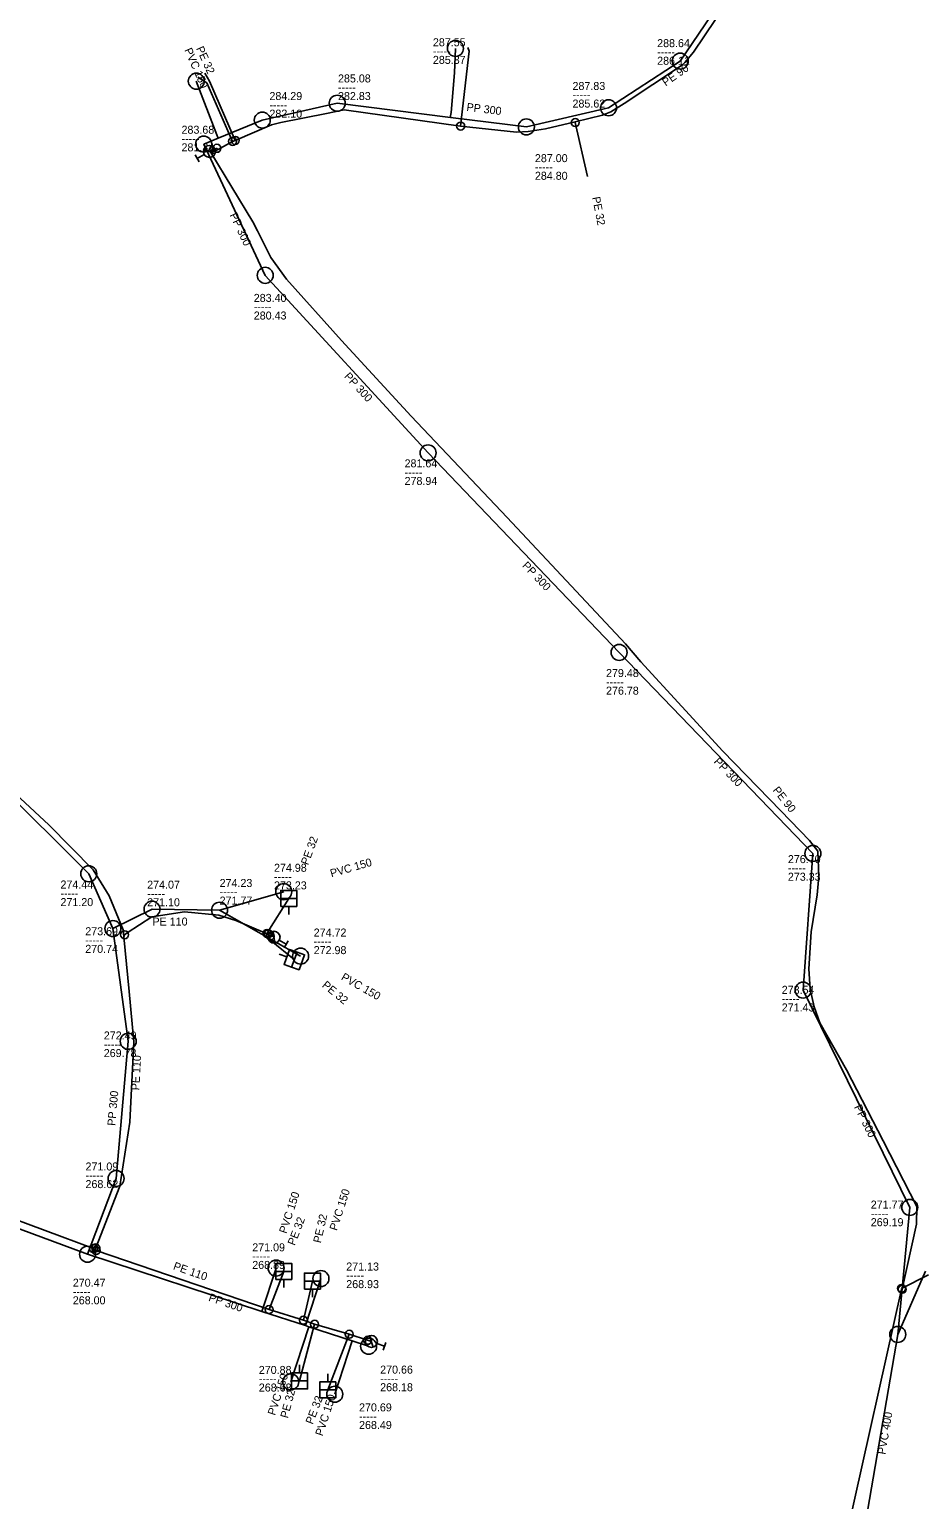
# Model space of a CAD drawing. Extents: x -770828 to -770111, y -1050344 to -1049447.
# Drawn here: x -770619.1 to -770507.8, y -1049725.3 to -1049541.6 of the extents above; entities that cross this region are included whole.
import ezdxf

# ---------------------------------------------------------------- set-up
doc = ezdxf.new("R2010")
doc.units = 0
doc.layers.add('Level 0', color=7, linetype='Continuous')

msp = doc.modelspace()

# ---------------------------------------------------------------- linework, layer by layer
at = {"layer": 'Level 0'}
for p, q in [((-770532.05, -1049537.18), (-770537.74, -1049545.57)), ((-770536.06, -1049544.45), (-770531.94, -1049538.32)), ((-770565.83, -1049543.99), (-770565.94, -1049547.05)), ((-770564.1, -1049544.35), (-770565.18, -1049553.69)), ((-770564.29, -1049543.88), (-770564.1, -1049544.35)), ((-770537.16, -1049545.75), (-770536.06, -1049544.45)), ((-770537.74, -1049545.57), (-770546.69, -1049551.41)), ((-770544.73, -1049550.86), (-770537.57, -1049546.11)), ((-770537.57, -1049546.11), (-770537.16, -1049545.75)), ((-770598.22, -1049548.08), (-770595.67, -1049554.78)), ((-770598.04, -1049547.59), (-770596.92, -1049548.29)), ((-770597.14, -1049547.08), (-770596.59, -1049548.1)), ((-770596.92, -1049548.29), (-770593.68, -1049555.6)), ((-770596.59, -1049548.1), (-770593.36, -1049555.48)), ((-770565.94, -1049547.05), (-770566.37, -1049551.98)), ((-770580.61, -1049550.84), (-770589.97, -1049552.94)), ((-770587.67, -1049553.23), (-770581.96, -1049552.1)), ((-770581.96, -1049552.1), (-770579.73, -1049551.68)), ((-770566.45, -1049552.61), (-770580.6, -1049550.84)), ((-770579.73, -1049551.68), (-770565.18, -1049553.69)), ((-770566.37, -1049551.98), (-770566.43, -1049552.43)), ((-770546.69, -1049551.41), (-770556.97, -1049553.8)), ((-770547.46, -1049552.33), (-770546.41, -1049551.93)), ((-770546.41, -1049551.93), (-770544.73, -1049550.86)), ((-770589.97, -1049552.94), (-770595.49, -1049555.2)), ((-770593.36, -1049555.48), (-770588.82, -1049553.52)), ((-770588.82, -1049553.52), (-770587.67, -1049553.23)), ((-770566.43, -1049552.43), (-770566.45, -1049552.61)), ((-770556.97, -1049553.8), (-770566.45, -1049552.61)), ((-770565.18, -1049553.69), (-770558.22, -1049554.44)), ((-770556.74, -1049554.35), (-770554.56, -1049554.05)), ((-770554.56, -1049554.05), (-770550.88, -1049553.16)), ((-770550.88, -1049553.16), (-770547.46, -1049552.33)), ((-770550.86, -1049553.26), (-770550.88, -1049553.16)), ((-770549.34, -1049559.99), (-770550.86, -1049553.26)), ((-770595.49, -1049555.2), (-770597.3, -1049555.94)), ((-770595.67, -1049554.78), (-770595.53, -1049555.1)), ((-770595.59, -1049556.66), (-770593.68, -1049555.6)), ((-770595.53, -1049555.1), (-770595.49, -1049555.2)), ((-770593.68, -1049555.6), (-770593.36, -1049555.48)), ((-770558.22, -1049554.44), (-770556.74, -1049554.35)), ((-770597.85, -1049558.17), (-770598.35, -1049557.3)), ((-770597.23, -1049557.24), (-770598.1, -1049557.74)), ((-770597.3, -1049555.94), (-770589.61, -1049572.34)), ((-770595.89, -1049557.14), (-770597.28, -1049556.58)), ((-770596.58, -1049556.86), (-770595.65, -1049556.47)), ((-770595.59, -1049556.66), (-770596.39, -1049556.98)), ((-770596.39, -1049556.98), (-770591.14, -1049565.64)), ((-770595.65, -1049556.47), (-770595.59, -1049556.66)), ((-770591.14, -1049565.64), (-770590.57, -1049566.78)), ((-770590.57, -1049566.78), (-770588.9, -1049570.13)), ((-770588.9, -1049570.13), (-770586.95, -1049572.83)), ((-770589.61, -1049572.34), (-770569.25, -1049594.52)), ((-770586.95, -1049572.83), (-770580.07, -1049580.47)), ((-770580.07, -1049580.47), (-770571.37, -1049589.93)), ((-770571.37, -1049589.93), (-770559.36, -1049602.58)), ((-770569.25, -1049594.52), (-770545.37, -1049619.45)), ((-770559.36, -1049602.58), (-770544.56, -1049618.37)), ((-770544.56, -1049618.37), (-770542.68, -1049620.64)), ((-770545.37, -1049619.45), (-770521.15, -1049644.57)), ((-770542.68, -1049620.64), (-770532.41, -1049631.78)), ((-770635.31, -1049623.57), (-770611.67, -1049647.11)), ((-770532.41, -1049631.78), (-770525.17, -1049639.26)), ((-770623.69, -1049634.47), (-770616.65, -1049641)), ((-770525.17, -1049639.26), (-770521.59, -1049642.95)), ((-770616.65, -1049641), (-770611.11, -1049646.6)), ((-770521.59, -1049642.95), (-770520.55, -1049644.27)), ((-770521.15, -1049644.57), (-770522.38, -1049661.65)), ((-770520.55, -1049644.27), (-770520.4, -1049647.46)), ((-770611.67, -1049647.11), (-770608.64, -1049653.95)), ((-770611.11, -1049646.6), (-770609.1, -1049649.87)), ((-770520.4, -1049647.46), (-770520.64, -1049649.75)), ((-770587.29, -1049649.35), (-770595.31, -1049651.66)), ((-770609.1, -1049649.87), (-770607.35, -1049654.12)), ((-770586.67, -1049650.19), (-770589.3, -1049654.38)), ((-770586.67, -1049652.19), (-770586.67, -1049651.19)), ((-770520.64, -1049649.75), (-770521.38, -1049654.38)), ((-770603.76, -1049651.53), (-770608.64, -1049653.95)), ((-770603.8, -1049652.47), (-770606.87, -1049654.5)), ((-770599.69, -1049651.88), (-770603.8, -1049652.47)), ((-770595.31, -1049651.66), (-770603.76, -1049651.53)), ((-770595.4, -1049652.28), (-770599.69, -1049651.88)), ((-770593.28, -1049652.93), (-770595.4, -1049652.28)), ((-770585.18, -1049657.4), (-770595.31, -1049651.66)), ((-770589.65, -1049654.48), (-770593.28, -1049652.93)), ((-770608.64, -1049653.95), (-770606.73, -1049668.04)), ((-770607.35, -1049654.12), (-770607.27, -1049654.99)), ((-770607.19, -1049654.72), (-770607.27, -1049654.99)), ((-770607.27, -1049654.99), (-770606.62, -1049661.82)), ((-770606.87, -1049654.5), (-770607.19, -1049654.72)), ((-770589.46, -1049654.62), (-770589.65, -1049654.48)), ((-770589.37, -1049654.57), (-770589.46, -1049654.62)), ((-770589.26, -1049654.66), (-770589.46, -1049654.62)), ((-770589.3, -1049654.38), (-770589.37, -1049654.57)), ((-770589.22, -1049654.61), (-770589.27, -1049655.15)), ((-770589.26, -1049654.66), (-770589.22, -1049654.61)), ((-770588.99, -1049654.9), (-770589.26, -1049654.66)), ((-770588.67, -1049654.92), (-770588.99, -1049654.9)), ((-770588.5, -1049655.04), (-770588.67, -1049654.92)), ((-770588.61, -1049654.3), (-770588.39, -1049655.78)), ((-770521.38, -1049654.38), (-770521.67, -1049658.98)), ((-770589.27, -1049655.15), (-770588.87, -1049655.48)), ((-770588.87, -1049655.48), (-770585.97, -1049657.83)), ((-770587.85, -1049655.42), (-770586.98, -1049655.92)), ((-770586.73, -1049655.48), (-770587.23, -1049656.35)), ((-770587.85, -1049657.15), (-770586.91, -1049657.49)), ((-770521.67, -1049658.98), (-770521.48, -1049661.52)), ((-770606.62, -1049661.82), (-770606.04, -1049668.12)), ((-770522.38, -1049661.65), (-770509.04, -1049688.79)), ((-770521.48, -1049661.52), (-770521, -1049663.72)), ((-770521, -1049663.72), (-770520.27, -1049665.72)), ((-770520.27, -1049665.72), (-770516.95, -1049671.6)), ((-770606.73, -1049668.04), (-770608.24, -1049685.18)), ((-770606.04, -1049668.12), (-770606.54, -1049678.14)), ((-770516.95, -1049671.6), (-770512.35, -1049680.47)), ((-770606.54, -1049678.14), (-770607.76, -1049686.16)), ((-770512.35, -1049680.47), (-770508.16, -1049688.67)), ((-770611.09, -1049693.93), (-770631.73, -1049686.21)), ((-770608.24, -1049685.18), (-770611.82, -1049694.65)), ((-770607.76, -1049686.16), (-770610.79, -1049693.85)), ((-770611.82, -1049694.65), (-770632.71, -1049686.85)), ((-770509.04, -1049688.79), (-770510.55, -1049704.66)), ((-770508.16, -1049688.67), (-770508.2, -1049690.88)), ((-770508.2, -1049690.88), (-770509.98, -1049699.02)), ((-770590.02, -1049701.78), (-770611.82, -1049694.65)), ((-770611.09, -1049693.93), (-770610.9, -1049694.07)), ((-770610.79, -1049693.85), (-770610.9, -1049694.07)), ((-770610.75, -1049694.18), (-770610.9, -1049694.07)), ((-770589.13, -1049701.56), (-770610.75, -1049694.18)), ((-770588.25, -1049696.37), (-770590.02, -1049701.78)), ((-770587.29, -1049696.79), (-770589.13, -1049701.56)), ((-770507.09, -1049696.75), (-770510.55, -1049704.66)), ((-770506.69, -1049697.21), (-770510.06, -1049698.91)), ((-770587.29, -1049698.79), (-770587.29, -1049697.79)), ((-770583.71, -1049697.99), (-770584.84, -1049702.9)), ((-770582.64, -1049697.68), (-770584.56, -1049703.56)), ((-770583.71, -1049699.99), (-770583.71, -1049698.99)), ((-770519.6, -1049741.56), (-770510.08, -1049699.01)), ((-770510.08, -1049699.01), (-770510.06, -1049698.91)), ((-770509.98, -1049699.02), (-770510.08, -1049699.01)), ((-770584.56, -1049703.56), (-770590.02, -1049701.78)), ((-770584.84, -1049702.9), (-770589.13, -1049701.56)), ((-770586.41, -1049710.6), (-770584.15, -1049703.7)), ((-770585.32, -1049710.47), (-770583.44, -1049703.39)), ((-770583.44, -1049703.39), (-770584.84, -1049702.9)), ((-770584.15, -1049703.7), (-770584.56, -1049703.56)), ((-770578.73, -1049705.47), (-770584.15, -1049703.7)), ((-770579.11, -1049704.64), (-770583.44, -1049703.39)), ((-770581.78, -1049711.58), (-770579.11, -1049704.64)), ((-770576.82, -1049705.4), (-770579.11, -1049704.64)), ((-770510.55, -1049704.66), (-770515.63, -1049734.44)), ((-770580.91, -1049712.14), (-770578.73, -1049705.47)), ((-770576.68, -1049706.14), (-770578.73, -1049705.47)), ((-770576.34, -1049705.54), (-770576.82, -1049705.4)), ((-770576.57, -1049704.83), (-770576.11, -1049706.25)), ((-770575.64, -1049705.8), (-770574.7, -1049706.14)), ((-770574.52, -1049705.67), (-770574.87, -1049706.61)), ((-770585.32, -1049708.47), (-770585.32, -1049709.47)), ((-770581.78, -1049709.58), (-770581.78, -1049710.58))]:
    msp.add_line(p, q, dxfattribs=at)
for points in [[(-770587.67, -1049650.19), (-770587.67, -1049649.19), (-770585.67, -1049649.19), (-770585.67, -1049650.19)], [(-770585.63, -1049656.89), (-770584.69, -1049657.23), (-770585.37, -1049659.11), (-770586.31, -1049658.77)], [(-770588.29, -1049696.79), (-770588.29, -1049695.79), (-770586.29, -1049695.79), (-770586.29, -1049696.79)], [(-770584.71, -1049697.99), (-770584.71, -1049696.99), (-770582.71, -1049696.99), (-770582.71, -1049697.99)], [(-770584.32, -1049710.47), (-770584.32, -1049711.47), (-770586.32, -1049711.47), (-770586.32, -1049710.47)], [(-770580.78, -1049711.58), (-770580.78, -1049712.58), (-770582.78, -1049712.58), (-770582.78, -1049711.58)]]:
    msp.add_lwpolyline(points, dxfattribs=at)
for points in [[(-770587.67, -1049651.19), (-770585.67, -1049651.19), (-770585.67, -1049650.19), (-770587.67, -1049650.19)], [(-770586.57, -1049656.55), (-770587.25, -1049658.43), (-770586.31, -1049658.77), (-770585.63, -1049656.89)], [(-770588.29, -1049697.79), (-770586.29, -1049697.79), (-770586.29, -1049696.79), (-770588.29, -1049696.79)], [(-770584.71, -1049698.99), (-770582.71, -1049698.99), (-770582.71, -1049697.99), (-770584.71, -1049697.99)], [(-770584.32, -1049709.47), (-770586.32, -1049709.47), (-770586.32, -1049710.47), (-770584.32, -1049710.47)], [(-770580.78, -1049710.58), (-770582.78, -1049710.58), (-770582.78, -1049711.58), (-770580.78, -1049711.58)]]:
    msp.add_lwpolyline(points, close=True, dxfattribs=at)
for centre, radius in [((-770565.83, -1049543.99), 1), ((-770537.74, -1049545.57), 1), ((-770598.22, -1049548.08), 1), ((-770580.6, -1049550.84), 1), ((-770546.69, -1049551.41), 1), ((-770589.97, -1049552.94), 1), ((-770565.18, -1049553.69), 0.5), ((-770556.97, -1049553.8), 1), ((-770550.86, -1049553.26), 0.5), ((-770597.3, -1049555.94), 1), ((-770593.68, -1049555.6), 0.5), ((-770593.36, -1049555.48), 0.5), ((-770596.58, -1049556.86), 0.75), ((-770595.65, -1049556.47), 0.5), ((-770589.61, -1049572.34), 1), ((-770569.25, -1049594.52), 1), ((-770545.37, -1049619.45), 1), ((-770521.15, -1049644.57), 1), ((-770611.67, -1049647.11), 1), ((-770587.29, -1049649.35), 1), ((-770603.76, -1049651.53), 1), ((-770595.31, -1049651.66), 1), ((-770608.64, -1049653.95), 1), ((-770607.19, -1049654.72), 0.5), ((-770589.37, -1049654.57), 0.5), ((-770589.22, -1049654.61), 0.5), ((-770588.99, -1049654.9), 0.5), ((-770588.5, -1049655.04), 0.75), ((-770585.18, -1049657.4), 1), ((-770522.38, -1049661.65), 1), ((-770606.73, -1049668.04), 1), ((-770608.24, -1049685.18), 1), ((-770509.04, -1049688.79), 1), ((-770611.82, -1049694.65), 1), ((-770611.09, -1049693.93), 0.5), ((-770610.79, -1049693.85), 0.5), ((-770610.75, -1049694.18), 0.5), ((-770588.25, -1049696.37), 1), ((-770582.64, -1049697.68), 1), ((-770510.06, -1049698.91), 0.5), ((-770509.98, -1049699.02), 0.5), ((-770589.13, -1049701.56), 0.5), ((-770584.84, -1049702.9), 0.5), ((-770583.44, -1049703.39), 0.5), ((-770579.11, -1049704.64), 0.5), ((-770510.55, -1049704.66), 1), ((-770576.68, -1049706.14), 1), ((-770576.82, -1049705.4), 0.5), ((-770576.34, -1049705.54), 0.75), ((-770586.41, -1049710.6), 1), ((-770580.91, -1049712.14), 1)]:
    msp.add_circle(centre, radius, dxfattribs=at)

# ---------------------------------------------------------------- texts
for s, p in [('287.55', (-770568.65, -1049543.72)), ('288.64', (-770540.62, -1049543.83)), ('-----', (-770568.65, -1049544.82)), ('285.37', (-770568.65, -1049545.92)), ('-----', (-770540.62, -1049544.93)), ('286.11', (-770540.62, -1049546.03)), ('285.08', (-770580.51, -1049548.24)), ('287.83', (-770551.2, -1049549.18)), ('284.29', (-770589.08, -1049550.44)), ('-----', (-770580.51, -1049549.34)), ('282.83', (-770580.51, -1049550.44)), ('-----', (-770551.2, -1049550.28)), ('285.62', (-770551.2, -1049551.38)), ('-----', (-770589.08, -1049551.54)), ('282.10', (-770589.08, -1049552.64)), ('283.68', (-770600.07, -1049554.65)), ('-----', (-770600.07, -1049555.75)), ('281.34', (-770600.07, -1049556.85)), ('287.00', (-770555.9, -1049558.2)), ('-----', (-770555.9, -1049559.3)), ('284.80', (-770555.9, -1049560.4)), ('283.40', (-770591.04, -1049575.66)), ('-----', (-770591.04, -1049576.76)), ('280.43', (-770591.04, -1049577.86)), ('281.64', (-770572.19, -1049596.33)), ('-----', (-770572.19, -1049597.43)), ('278.94', (-770572.19, -1049598.53)), ('279.48', (-770547.01, -1049622.53)), ('-----', (-770547.01, -1049623.63)), ('276.78', (-770547.01, -1049624.73)), ('274.98', (-770588.51, -1049646.86)), ('276.70', (-770524.28, -1049645.78)), ('274.23', (-770595.31, -1049648.76)), ('-----', (-770588.51, -1049647.96)), ('-----', (-770524.28, -1049646.88)), ('273.33', (-770524.28, -1049647.98)), ('-----', (-770615.2, -1049650.05)), ('274.44', (-770615.2, -1049648.95)), ('274.07', (-770604.36, -1049648.97)), ('-----', (-770595.31, -1049649.86)), ('273.23', (-770588.51, -1049649.06)), ('271.20', (-770615.2, -1049651.15)), ('-----', (-770604.36, -1049650.07)), ('271.10', (-770604.36, -1049651.17)), ('271.77', (-770595.31, -1049650.96)), ('PE 110', (-770603.7, -1049653.58)), ('273.69', (-770612.1, -1049654.79)), ('274.72', (-770583.55, -1049654.95)), ('-----', (-770612.1, -1049655.89)), ('270.74', (-770612.1, -1049656.99)), ('-----', (-770583.55, -1049656.05)), ('272.98', (-770583.55, -1049657.15)), ('273.54', (-770525.05, -1049662.11)), ('-----', (-770525.05, -1049663.21)), ('271.43', (-770525.05, -1049664.31)), ('272.49', (-770609.79, -1049667.81)), ('-----', (-770609.79, -1049668.91)), ('269.78', (-770609.79, -1049670.01)), ('271.09', (-770612.07, -1049684.18)), ('-----', (-770612.07, -1049685.28)), ('268.62', (-770612.07, -1049686.38)), ('271.77', (-770513.92, -1049688.94)), ('-----', (-770513.92, -1049690.04)), ('269.19', (-770513.92, -1049691.14)), ('271.09', (-770591.23, -1049694.28)), ('-----', (-770591.23, -1049695.38)), ('268.89', (-770591.23, -1049696.48)), ('-----', (-770579.48, -1049697.78)), ('271.13', (-770579.48, -1049696.68)), ('270.47', (-770613.66, -1049698.7)), ('268.93', (-770579.48, -1049698.88)), ('-----', (-770613.66, -1049699.8)), ('268.00', (-770613.66, -1049700.9)), ('270.88', (-770590.41, -1049709.6)), ('-----', (-770575.24, -1049710.66)), ('270.66', (-770575.24, -1049709.56)), ('-----', (-770590.41, -1049710.7)), ('268.68', (-770590.41, -1049711.8)), ('268.18', (-770575.24, -1049711.76)), ('270.69', (-770577.88, -1049714.28)), ('-----', (-770577.88, -1049715.38)), ('268.49', (-770577.88, -1049716.48))]:
    msp.add_text(s, height=1, dxfattribs=at).set_placement(p)
for s, rotation, p in [('PVC 150', 293.629, (-770599.74, -1049544.18)), ('PE 32', 294.228, (-770598.27, -1049543.99)), ('PE 90', 35, (-770539.55, -1049548.76)), ('PP 300', 352.87, (-770564.49, -1049551.78)), ('PE 32', 281.061, (-770548.75, -1049562.61)), ('PP 300', 295.122, (-770594.08, -1049564.8)), ('PP 300', 312.55, (-770579.81, -1049585.02)), ('PP 300', 313.768, (-770557.56, -1049608.68)), ('PP 300', 313.955, (-770533.61, -1049633.16)), ('PE 90', 308.234, (-770526.23, -1049636.69)), ('PE 32', 69.775, (-770584.25, -1049646.09)), ('PVC 150', 16.068, (-770581.33, -1049647.57)), ('PE 32', 320.477, (-770582.58, -1049661.17)), ('PVC 150', 330.463, (-770580.21, -1049660.3)), ('PE 110', 87.143, (-770605.34, -1049674.18)), ('PP 300', 84.965, (-770608.35, -1049678.63)), ('PP 300', 296.175, (-770516.04, -1049676.24)), ('PVC 150', 71.883, (-770586.96, -1049692.13)), ('PVC 150', 71.917, (-770580.66, -1049691.77)), ('PE 32', 68.906, (-770585.92, -1049693.63)), ('PE 32', 77.039, (-770582.66, -1049693.31)), ('PE 110', 340.71, (-770601.19, -1049696.52)), ('PP 300', 341.147, (-770596.77, -1049700.45)), ('PVC 150', 71.865, (-770588.39, -1049714.85)), ('PE 32', 75.129, (-770586.78, -1049715.2)), ('PE 32', 68.957, (-770583.68, -1049715.97)), ('PVC 150', 71.901, (-770582.44, -1049717.43)), ('PVC 400', 80.319, (-770512.1, -1049719.72))]:
    msp.add_text(s, height=1, rotation=rotation, dxfattribs=at).set_placement(p)

doc.saveas('drawing.dxf')
